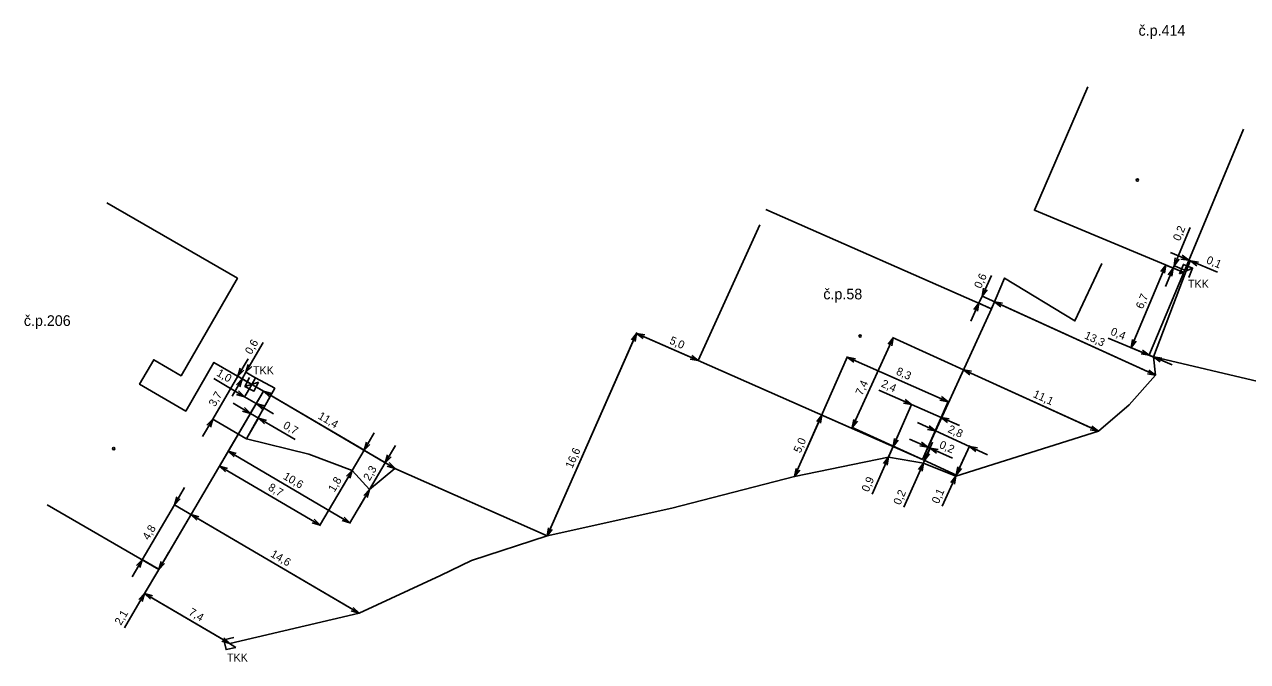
# Model space of a CAD drawing. Extents: x -770877 to -770229, y -1050342 to -1050226.
# Drawn here: x -770876.9 to -770785.2, y -1050297.6 to -1050249.9 of the extents above; entities that cross this region are included whole.
import ezdxf

# ---------------------------------------------------------------- set-up
doc = ezdxf.new("R2010")
doc.units = 0
for name, color, linetype in [('f001_pol_linie', 7, 'Continuous'), ('f001_pol_znacky', 7, 'Continuous'), ('f003_opt_sit_texty', 7, 'Continuous'), ('f003_opt_sit_znacky', 7, 'Continuous'), ('f006_osa_trasy', 7, 'Continuous'), ('f006_stp_koty', 7, 'Continuous'), ('Inspire adresy', 7, 'Continuous')]:
    doc.layers.add(name, color=color, linetype=linetype)

msp = doc.modelspace()

# ---------------------------------------------------------------- linework, layer by layer
at = {"layer": 'f001_pol_linie'}
for points in [[(-770797.19, -1050254.56), (-770801.18, -1050263.81), (-770789.99, -1050268.48), (-770785.51, -1050257.74)], [(-770875.18, -1050285.88), (-770866.81, -1050290.73), (-770858.96, -1050277.37), (-770862.67, -1050275.22), (-770864.78, -1050278.86), (-770868.25, -1050276.85), (-770867.18, -1050275.02), (-770865.13, -1050276.21), (-770860.91, -1050268.91), (-770870.71, -1050263.25)], [(-770821.77, -1050264.9), (-770826.38, -1050275.08), (-770809.57, -1050282.5), (-770804.41, -1050271.19), (-770821.3, -1050263.75)], [(-770804.41, -1050271.19), (-770803.42, -1050268.9), (-770798.14, -1050272.1), (-770796.14, -1050267.81)]]:
    msp.add_lwpolyline(points, dxfattribs=at)
at = {"layer": 'f001_pol_znacky'}
for centre in [(-770793.459, -1050261.551), (-770814.241, -1050273.241), (-770870.186, -1050281.672)]:
    msp.add_circle(centre, 0.0875, dxfattribs=at)
at = {"layer": 'f003_opt_sit_znacky'}
for p, q in [((-770790.298, -1050268.568), (-770789.322, -1050268.152)), ((-770859.334, -1050276.7), (-770860.346, -1050277.02)), ((-770861.033, -1050296.576), (-770861.927, -1050296.004))]:
    msp.add_line(p, q, dxfattribs=at)
for points in [[(-770789.602, -1050268.848), (-770789.322, -1050268.152), (-770790.018, -1050267.872), (-770790.298, -1050268.568)], [(-770860, -1050276.354), (-770860.346, -1050277.02), (-770859.68, -1050277.366), (-770859.334, -1050276.7)], [(-770861.194, -1050295.843), (-770861.927, -1050296.004), (-770861.766, -1050296.737), (-770861.033, -1050296.576)]]:
    msp.add_lwpolyline(points, dxfattribs=at)
at = {"layer": 'f006_osa_trasy'}
for points in [[(-770843.38, -1050290.07), (-770837.7, -1050288.22), (-770828.36, -1050286.13), (-770819.15, -1050283.77), (-770812.12, -1050282.31), (-770809.5, -1050282.76), (-770807.07, -1050283.73), (-770796.39, -1050280.38), (-770794.09, -1050278.39), (-770792.11, -1050276.18), (-770792.25, -1050274.81), (-770789.81, -1050268.36)], [(-770792.25, -1050274.81), (-770784, -1050276.75), (-770779.3, -1050277.41), (-770778.4, -1050277.12), (-770757.45, -1050288.13)], [(-770859.84, -1050276.86), (-770859.56, -1050276.37), (-770858.12, -1050277.15), (-770860.24, -1050280.95), (-770855.57, -1050282.09), (-770852.31, -1050283.31), (-770851.01, -1050284.74), (-770849.11, -1050283.18), (-770837.7, -1050288.22)], [(-770861.48, -1050296.29), (-770851.79, -1050294.02), (-770845.7, -1050291.19), (-770843.38, -1050290.07)]]:
    msp.add_lwpolyline(points, dxfattribs=at)
at = {"layer": 'f006_stp_koty'}
for p, q in [((-770789.513, -1050265.101), (-770790.715, -1050267.983)), ((-770790.99, -1050266.981), (-770789.606, -1050267.559)), ((-770793.926, -1050274.11), (-770791.341, -1050267.916)), ((-770790.045, -1050268.457), (-770791.397, -1050267.893)), ((-770791.361, -1050269.533), (-770790.784, -1050268.149)), ((-770790.045, -1050268.457), (-770790.839, -1050268.126)), ((-770790.784, -1050268.149), (-770790.715, -1050267.983)), ((-770789.865, -1050268.337), (-770790.77, -1050267.96)), ((-770789.967, -1050268.425), (-770789.583, -1050267.503)), ((-770789.787, -1050268.305), (-770789.472, -1050267.549)), ((-770789.495, -1050267.605), (-770789.606, -1050267.559)), ((-770787.471, -1050268.449), (-770789.495, -1050267.605)), ((-770804.389, -1050268.693), (-770805.101, -1050270.253)), ((-770790.013, -1050268.535), (-770792.598, -1050274.73)), ((-770805.958, -1050272.132), (-770805.336, -1050270.768)), ((-770804.465, -1050271.165), (-770805.39, -1050270.743)), ((-770805.336, -1050270.768), (-770805.101, -1050270.253)), ((-770792.165, -1050276.155), (-770805.155, -1050270.228)), ((-770804.385, -1050271.135), (-770804.15, -1050270.621)), ((-770792.11, -1050276.18), (-770804.175, -1050270.675)), ((-770837.7, -1050288.22), (-770831, -1050273.041)), ((-770837.676, -1050288.165), (-770830.976, -1050272.986)), ((-770826.435, -1050275.056), (-770831.055, -1050273.017)), ((-770826.38, -1050275.08), (-770831, -1050273.041)), ((-770814.829, -1050280.101), (-770811.758, -1050273.369)), ((-770796.445, -1050280.355), (-770811.812, -1050273.344)), ((-770795.643, -1050273.394), (-770792.575, -1050274.674)), ((-770858.976, -1050273.722), (-770860.271, -1050275.958)), ((-770792.305, -1050274.787), (-770793.982, -1050274.087)), ((-770860.112, -1050274.953), (-770860.872, -1050276.247)), ((-770819.126, -1050283.715), (-770815.18, -1050274.776)), ((-770807.656, -1050278.162), (-770815.205, -1050274.831)), ((-770792.575, -1050274.674), (-770792.25, -1050274.81)), ((-770790.866, -1050275.388), (-770792.25, -1050274.81)), ((-770860.872, -1050276.247), (-770862.764, -1050279.467)), ((-770859.012, -1050277.34), (-770860.923, -1050276.216)), ((-770859.012, -1050277.34), (-770860.606, -1050276.416)), ((-770860.271, -1050275.958), (-770860.554, -1050276.446)), ((-770859.612, -1050276.34), (-770860.323, -1050275.928)), ((-770809.545, -1050282.445), (-770806.474, -1050275.713)), ((-770796.39, -1050280.38), (-770806.499, -1050275.768)), ((-770862.682, -1050276.434), (-770860.383, -1050277.785)), ((-770861.306, -1050277.744), (-770860.554, -1050276.446)), ((-770859.87, -1050276.912), (-770860.414, -1050277.836)), ((-770812.837, -1050277.29), (-770810.382, -1050278.373)), ((-770858.99, -1050277.422), (-770862.287, -1050283.033)), ((-770858.99, -1050277.422), (-770861.636, -1050281.924)), ((-770860.383, -1050277.785), (-770859.506, -1050278.3)), ((-770858.99, -1050277.422), (-770859.971, -1050279.091)), ((-770858.99, -1050277.422), (-770859.537, -1050278.352)), ((-770849.1, -1050283.163), (-770858.96, -1050277.37)), ((-770858.908, -1050277.4), (-770849.779, -1050282.764)), ((-770858.908, -1050277.4), (-770851.37, -1050281.829)), ((-770809.546, -1050282.445), (-770807.631, -1050278.107)), ((-770861.234, -1050278.279), (-770859.941, -1050279.039)), ((-770859.328, -1050279.399), (-770859.941, -1050279.039)), ((-770858.213, -1050279.06), (-770859.506, -1050278.3)), ((-770819.15, -1050283.77), (-770817.119, -1050279.168)), ((-770809.625, -1050282.476), (-770817.174, -1050279.144)), ((-770812.096, -1050282.255), (-770810.358, -1050278.318)), ((-770808.178, -1050279.346), (-770810.382, -1050278.373)), ((-770863.524, -1050280.76), (-770862.764, -1050279.467)), ((-770860.292, -1050280.92), (-770862.816, -1050279.437)), ((-770860.21, -1050280.898), (-770859.298, -1050279.347)), ((-770856.596, -1050281.004), (-770859.328, -1050279.399)), ((-770809.625, -1050282.475), (-770814.884, -1050280.076)), ((-770809.956, -1050279.732), (-770808.591, -1050280.354)), ((-770809.546, -1050282.445), (-770808.154, -1050279.291)), ((-770806.806, -1050279.952), (-770808.178, -1050279.346)), ((-770850.662, -1050280.506), (-770851.422, -1050281.799)), ((-770811.169, -1050280.155), (-770811.774, -1050281.527)), ((-770810.533, -1050280.968), (-770809.161, -1050281.574)), ((-770809.545, -1050282.445), (-770808.566, -1050280.3)), ((-770806.057, -1050281.51), (-770808.591, -1050280.354)), ((-770852.477, -1050287.236), (-770861.605, -1050281.872)), ((-770851.422, -1050281.799), (-770852.31, -1050283.31)), ((-770849.071, -1050281.441), (-770849.831, -1050282.734)), ((-770812.12, -1050282.31), (-770811.774, -1050281.527)), ((-770809.625, -1050282.476), (-770811.829, -1050281.503)), ((-770809.546, -1050282.445), (-770809.137, -1050281.519)), ((-770809.476, -1050282.705), (-770808.982, -1050281.587)), ((-770808.81, -1050281.196), (-770809.415, -1050282.568)), ((-770809.161, -1050281.574), (-770809.006, -1050281.642)), ((-770807.317, -1050282.387), (-770809.006, -1050281.642)), ((-770807.045, -1050283.675), (-770806.032, -1050281.456)), ((-770804.693, -1050282.133), (-770806.057, -1050281.51)), ((-770849.831, -1050282.734), (-770851.01, -1050284.74)), ((-770813.35, -1050285.096), (-770812.12, -1050282.31)), ((-770810.962, -1050286.073), (-770809.5, -1050282.76)), ((-770809.515, -1050282.524), (-770809.36, -1050282.592)), ((-770809.515, -1050282.525), (-770806.982, -1050283.681)), ((-770809.5, -1050282.76), (-770809.415, -1050282.568)), ((-770806.414, -1050282.291), (-770807.036, -1050283.656)), ((-770854.719, -1050287.41), (-770862.257, -1050282.981)), ((-770852.34, -1050283.362), (-770854.749, -1050287.462)), ((-770853.38, -1050285.131), (-770852.31, -1050283.31)), ((-770808.099, -1050285.986), (-770807.07, -1050283.73)), ((-770807.036, -1050283.656), (-770807.07, -1050283.73)), ((-770864.87, -1050284.595), (-770865.629, -1050285.888)), ((-770851.04, -1050284.792), (-770852.507, -1050287.288)), ((-770851.77, -1050286.033), (-770851.01, -1050284.74)), ((-770868.047, -1050290.003), (-770865.629, -1050285.888)), ((-770851.842, -1050293.99), (-770865.681, -1050285.858)), ((-770866.78, -1050290.678), (-770864.362, -1050286.563)), ((-770851.79, -1050294.02), (-770864.392, -1050286.615)), ((-770868.807, -1050291.296), (-770868.047, -1050290.003)), ((-770866.862, -1050290.7), (-770868.099, -1050289.973)), ((-770866.05, -1050289.437), (-770866.81, -1050290.73)), ((-770866.84, -1050290.782), (-770867.901, -1050292.587)), ((-770866.81, -1050290.73), (-770867.871, -1050292.535)), ((-770869.386, -1050295.115), (-770867.871, -1050292.535)), ((-770861.532, -1050296.26), (-770867.922, -1050292.505)), ((-770861.48, -1050296.29), (-770867.871, -1050292.535))]:
    msp.add_line(p, q, dxfattribs=at)
for points in [[(-770790.102, -1050267.189), (-770789.606, -1050267.559), (-770790.217, -1050267.466)], [(-770791.711, -1050268.412), (-770791.341, -1050267.916), (-770791.434, -1050268.528)], [(-770791.153, -1050268.645), (-770790.784, -1050268.149), (-770790.876, -1050268.76)], [(-770790.345, -1050267.487), (-770790.715, -1050267.983), (-770790.622, -1050267.371)], [(-770788.999, -1050267.974), (-770789.495, -1050267.605), (-770788.883, -1050267.697)], [(-770804.715, -1050269.77), (-770805.101, -1050270.253), (-770804.988, -1050269.645)], [(-770805.721, -1050271.251), (-770805.336, -1050270.768), (-770805.448, -1050271.376)], [(-770803.692, -1050271.061), (-770804.175, -1050270.675), (-770803.567, -1050270.788)], [(-770831.379, -1050273.529), (-770831, -1050273.041), (-770831.105, -1050273.65)], [(-770830.512, -1050273.42), (-770831, -1050273.041), (-770830.39, -1050273.146)], [(-770812.143, -1050273.852), (-770811.758, -1050273.369), (-770811.87, -1050273.977)], [(-770793.557, -1050273.614), (-770793.926, -1050274.11), (-770793.834, -1050273.499)], [(-770793.071, -1050274.305), (-770792.575, -1050274.674), (-770793.187, -1050274.582)], [(-770859.841, -1050275.514), (-770860.271, -1050275.958), (-770860.1, -1050275.364)], [(-770826.868, -1050274.7), (-770826.38, -1050275.08), (-770826.989, -1050274.975)], [(-770814.716, -1050275.21), (-770815.205, -1050274.831), (-770814.595, -1050274.936)], [(-770791.754, -1050275.18), (-770792.25, -1050274.81), (-770791.639, -1050274.903)], [(-770860.438, -1050275.805), (-770860.872, -1050276.247), (-770860.697, -1050275.653)], [(-770806.015, -1050276.154), (-770806.499, -1050275.768), (-770805.891, -1050275.881)], [(-770792.594, -1050275.794), (-770792.11, -1050276.18), (-770792.718, -1050276.067)], [(-770860.985, -1050276.89), (-770860.554, -1050276.446), (-770860.725, -1050277.04)], [(-770860.825, -1050277.351), (-770860.383, -1050277.785), (-770860.977, -1050277.61)], [(-770858.519, -1050277.803), (-770858.96, -1050277.37), (-770858.367, -1050277.545)], [(-770810.871, -1050277.994), (-770810.382, -1050278.373), (-770810.992, -1050278.268)], [(-770808.144, -1050277.783), (-770807.656, -1050278.162), (-770808.265, -1050278.057)], [(-770860.382, -1050278.606), (-770859.941, -1050279.039), (-770860.534, -1050278.864)], [(-770859.065, -1050278.733), (-770859.506, -1050278.3), (-770858.913, -1050278.474)], [(-770817.498, -1050279.657), (-770817.119, -1050279.168), (-770817.224, -1050279.778)], [(-770863.197, -1050279.908), (-770862.764, -1050279.467), (-770862.939, -1050280.06)], [(-770858.887, -1050279.832), (-770859.328, -1050279.399), (-770858.735, -1050279.573)], [(-770814.444, -1050279.617), (-770814.829, -1050280.101), (-770814.717, -1050279.492)], [(-770809.075, -1050279.969), (-770808.591, -1050280.354), (-770809.199, -1050280.242)], [(-770807.69, -1050279.725), (-770808.178, -1050279.346), (-770807.568, -1050279.451)], [(-770796.874, -1050279.994), (-770796.39, -1050280.38), (-770796.998, -1050280.267)], [(-770811.395, -1050281.039), (-770811.774, -1050281.527), (-770811.669, -1050280.918)], [(-770861.164, -1050282.305), (-770861.605, -1050281.872), (-770861.012, -1050282.047)], [(-770850.989, -1050281.358), (-770851.422, -1050281.799), (-770851.248, -1050281.206)], [(-770809.649, -1050281.194), (-770809.161, -1050281.574), (-770809.771, -1050281.469)], [(-770808.518, -1050282.021), (-770809.006, -1050281.642), (-770808.397, -1050281.747)], [(-770805.574, -1050281.896), (-770806.057, -1050281.51), (-770805.449, -1050281.623)], [(-770849.398, -1050282.293), (-770849.831, -1050282.734), (-770849.657, -1050282.141)], [(-770849.542, -1050282.73), (-770849.1, -1050283.163), (-770849.694, -1050282.989)], [(-770812.499, -1050282.798), (-770812.12, -1050282.31), (-770812.225, -1050282.919)], [(-770809.879, -1050283.248), (-770809.5, -1050282.76), (-770809.605, -1050283.369)], [(-770809.036, -1050282.08), (-770809.415, -1050282.568), (-770809.31, -1050281.959)], [(-770861.816, -1050283.414), (-770862.257, -1050282.981), (-770861.664, -1050283.156)], [(-770852.743, -1050283.751), (-770852.31, -1050283.31), (-770852.485, -1050283.903)], [(-770818.771, -1050283.282), (-770819.15, -1050283.77), (-770819.045, -1050283.161)], [(-770807.456, -1050284.214), (-770807.07, -1050283.73), (-770807.183, -1050284.338)], [(-770806.651, -1050283.172), (-770807.036, -1050283.656), (-770806.924, -1050283.048)], [(-770865.196, -1050285.447), (-770865.629, -1050285.888), (-770865.455, -1050285.295)], [(-770851.443, -1050285.181), (-770851.01, -1050284.74), (-770851.185, -1050285.333)], [(-770863.951, -1050287.049), (-770864.392, -1050286.615), (-770863.799, -1050286.79)], [(-770855.16, -1050286.977), (-770854.719, -1050287.41), (-770855.312, -1050287.235)], [(-770852.918, -1050286.803), (-770852.477, -1050287.236), (-770853.07, -1050287.061)], [(-770837.32, -1050287.732), (-770837.7, -1050288.22), (-770837.595, -1050287.611)], [(-770868.48, -1050290.444), (-770868.047, -1050290.003), (-770868.222, -1050290.596)], [(-770866.377, -1050290.289), (-770866.81, -1050290.73), (-770866.635, -1050290.137)], [(-770868.304, -1050292.976), (-770867.871, -1050292.535), (-770868.045, -1050293.128)], [(-770867.429, -1050292.968), (-770867.871, -1050292.535), (-770867.277, -1050292.71)], [(-770852.231, -1050293.587), (-770851.79, -1050294.02), (-770852.383, -1050293.845)], [(-770861.921, -1050295.857), (-770861.48, -1050296.29), (-770862.073, -1050296.115)]]:
    msp.add_lwpolyline(points, dxfattribs=at)

# ---------------------------------------------------------------- texts
at = {"layer": 'f003_opt_sit_texty'}
for p in [(-770789.672, -1050269.625), (-770859.747, -1050276.106), (-770861.695, -1050297.636)]:
    msp.add_text('TKK', height=0.6, dxfattribs=at).set_placement(p)
at = {"layer": 'f006_stp_koty'}
for s, rotation, p in [('0,2', 67.35741, (-770790.281, -1050266.163)), ('0,1', 337.35741, (-770788.345, -1050267.759)), ('0,6', 65.47594, (-770805.192, -1050269.729)), ('6,7', 67.34742, (-770793.061, -1050271.259)), ('0,4', 337.34742, (-770795.527, -1050273.117)), ('0,6', 59.90707, (-770859.875, -1050274.675)), ('5,0', 336.18315, (-770828.584, -1050273.779)), ('13,3', 335.47594, (-770797.489, -1050273.396)), ('1,0', 329.56258, (-770862.53, -1050276.175)), ('8,3', 336.18535, (-770811.597, -1050276.095)), ('7,4', 65.47594, (-770814.085, -1050277.747)), ('2,4', 336.18535, (-770812.715, -1050277.015)), ('11,1', 335.47594, (-770801.337, -1050277.793)), ('3,7', 59.56258, (-770862.594, -1050278.585)), ('11,4', 329.56258, (-770854.924, -1050279.394)), ('0,7', 329.56258, (-770857.543, -1050280.099)), ('2,8', 335.47594, (-770807.725, -1050280.42)), ('5,0', 66.18535, (-770818.721, -1050282.055)), ('16,6', 66.18315, (-770835.817, -1050283.211)), ('0,2', 336.18535, (-770808.363, -1050281.598)), ('10,6', 329.56258, (-770857.54, -1050283.913)), ('2,3', 59.56258, (-770851.006, -1050284.141)), ('8,7', 329.56258, (-770858.666, -1050284.743)), ('1,8', 59.56258, (-770853.639, -1050284.979)), ('0,9', 66.18535, (-770813.624, -1050284.975)), ('0,2', 66.18535, (-770811.237, -1050285.952)), ('0,1', 65.47594, (-770808.372, -1050285.862)), ('4,8', 59.56258, (-770867.561, -1050288.583)), ('14,6', 329.56258, (-770858.483, -1050289.739)), ('7,4', 329.56258, (-770864.62, -1050294.097)), ('2,1', 59.56258, (-770869.645, -1050294.963))]:
    msp.add_text(s, height=0.6, rotation=rotation, dxfattribs=at).set_placement(p)
at = {"layer": 'Inspire adresy'}
for s, p in [('č.p.414', (-770793.378, -1050250.733)), ('č.p.58', (-770817, -1050270.493)), ('č.p.206', (-770876.919, -1050272.483))]:
    msp.add_text(s, height=0.8, dxfattribs=at).set_placement(p)

doc.saveas('drawing.dxf')
